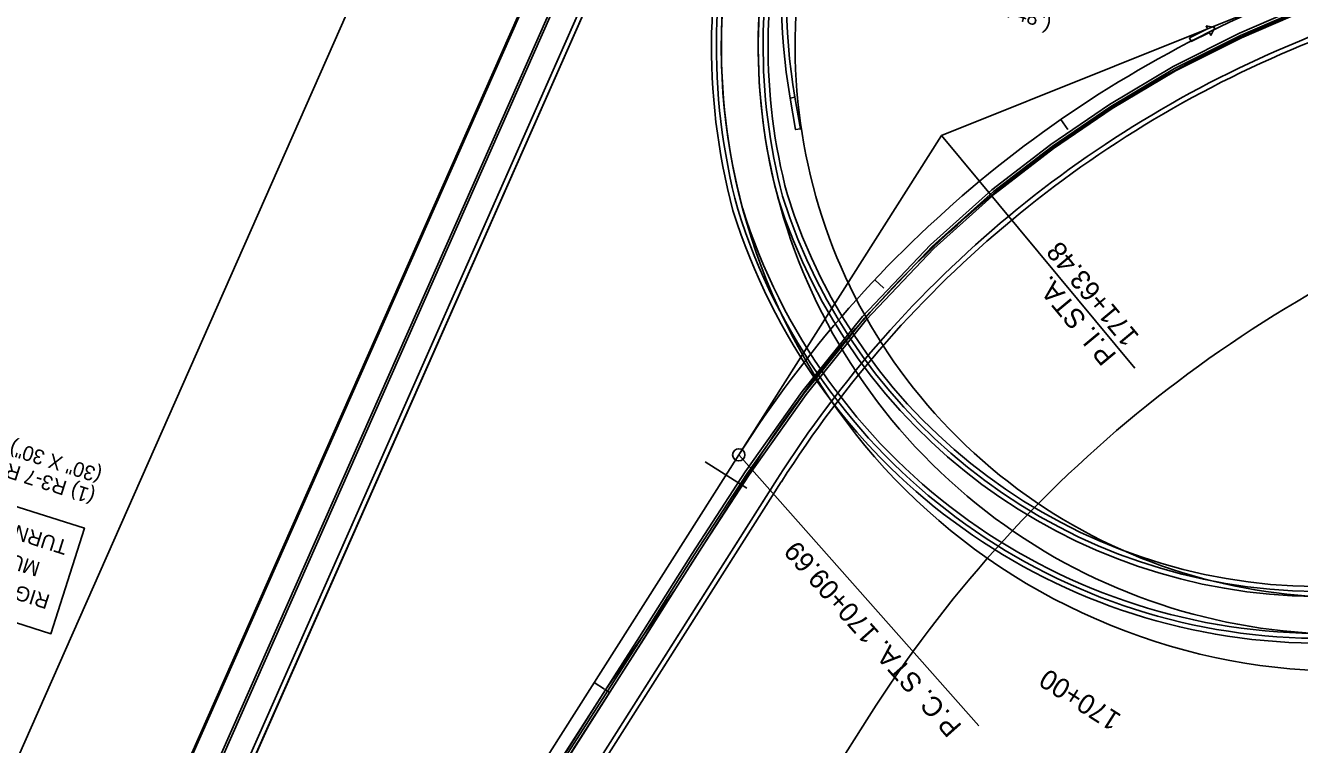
# Model space of a CAD drawing. Extents: x 659657 to 668193, y 633084 to 648639.
# Drawn here: x 661821 to 662339, y 641864 to 642156 of the extents above; entities that cross this region are included whole.
import ezdxf

# ---------------------------------------------------------------- set-up
doc = ezdxf.new("R2010")
doc.units = 0
for name, color, linetype in [('R_Border Prem', 7, 'Continuous'), ('R_MOT_Stage 1A', 7, 'Continuous'), ('R_MOT_Stage 1A_Striping', 7, 'Continuous'), ('R_MOT_Stage 1B', 7, 'Continuous'), ('R_MOT_Stage 1B_Striping', 7, 'Continuous'), ('R_MOT_Stage 1C', 7, 'Continuous'), ('R_MOT_Stage 1C_Striping', 7, 'Continuous'), ('R_MOT_Stage 2', 7, 'Continuous'), ('R_MOT_Stage 2_Striping', 7, 'Continuous'), ('R_MOT_Stage 3', 7, 'Continuous'), ('R_MOT_Stage 3_Striping', 7, 'Continuous'), ('R_MOT_Stage 3_Striping_PPM', 7, 'Continuous'), ('R_MOT_Stage 4', 7, 'Continuous'), ('R_MOT_Stage 4_Striping', 7, 'Continuous'), ('R_MOT_Stage 4_Striping_PPM', 7, 'Continuous'), ('R_MOT_Stage 5_Striping_PPM', 7, 'Continuous'), ('R_ROW Annot', 7, 'Continuous'), ('S_EXISTING_ALIGNMENT', 7, 'Continuous'), ('T_SIGNAL CONTROL CABINET', 7, 'Continuous'), ('TEMP_SIGNAL_POLES_STAGE 3', 7, 'Continuous')]:
    doc.layers.add(name, color=color, linetype=linetype)

msp = doc.modelspace()

# ---------------------------------------------------------------- linework, layer by layer
at = {"layer": 'R_Border Prem'}
msp.add_line((661686.79, 641562.92), (662861.91, 644217.67), dxfattribs=at)
at = {"layer": 'R_MOT_Stage 1A'}
for points in [[(662027.38, 641840.52), (662048.99, 641874.22), (662070.58, 641907.89), (662092.01, 641941.66), (662113.5, 641974.84), (662136.77, 642007.5), (662161.29, 642037.97), (662188.9, 642067.14), (662213.92, 642089.54), (662237.82, 642107.91), (662261.72, 642124.18), (662287.62, 642139.66), (662314.59, 642153.12), (662341.29, 642164.63), (662369.17, 642175.81), (662397.15, 642186.64), (662412.11, 642192.63), (662439.78, 642204.17), (662466.92, 642216.62), (662485.76, 642227.77), (662499, 642237.13)], [(662029.07, 641839.44), (662050.67, 641873.14), (662072.26, 641906.81), (662093.7, 641940.58), (662115.16, 641973.72), (662138.37, 642006.29), (662162.79, 642036.66), (662190.29, 642065.71), (662215.2, 642088), (662238.99, 642106.29), (662262.8, 642122.49), (662288.59, 642137.9), (662315.44, 642151.3), (662342.06, 642162.78), (662369.91, 642173.95), (662397.88, 642184.78), (662412.86, 642190.78), (662440.59, 642202.33), (662467.85, 642214.84), (662486.85, 642226.09), (662500.16, 642235.5)]]:
    msp.add_lwpolyline(points, dxfattribs=at)
at = {"layer": 'R_MOT_Stage 1A_Striping'}
for p, q in [((662193.45, 642111.58), (662336.18, 642168.83)), ((662193.45, 642111.58), (662336.18, 642168.83)), ((662110.96, 641981.8), (662193.45, 642111.58)), ((662110.96, 641981.8), (662193.45, 642111.58)), ((661764.81, 641437.19), (662110.96, 641981.8))]:
    msp.add_line(p, q, dxfattribs=at)
for points in [[(662027.38, 641840.52), (662048.99, 641874.22), (662070.58, 641907.89), (662092.01, 641941.66), (662113.5, 641974.84), (662136.77, 642007.5), (662161.29, 642037.97), (662188.9, 642067.14), (662213.92, 642089.54), (662237.82, 642107.91), (662261.72, 642124.18), (662287.62, 642139.66), (662314.59, 642153.12), (662341.29, 642164.63), (662369.17, 642175.81), (662397.15, 642186.64), (662412.11, 642192.63), (662439.78, 642204.17), (662466.92, 642216.62), (662485.76, 642227.77), (662499, 642237.13)], [(662244.79, 642114), (662241.95, 642118.11)], [(662193.45, 642111.58), (662272.02, 642016.97)], [(662169.94, 642049.56), (662166.3, 642052.99)], [(662110.96, 641981.8), (662208.63, 641871.7)], [(662097.32, 641978.98), (662114.2, 641968.25)], [(662056.34, 641886.54), (662052.12, 641889.22)]]:
    msp.add_lwpolyline(points, dxfattribs=at)
msp.add_circle((662110.96, 641981.8), 2.5, dxfattribs=at)
msp.add_arc((662513.92, 641725.68), 477.46, 111.8548, 147.5604, dxfattribs=at)
at = {"layer": 'R_MOT_Stage 1B'}
for p, q in [((662096.24, 641920.42), (662128.26, 641970.8)), ((662029.07, 641814.74), (662096.24, 641920.42)), ((661828.79, 641527.59), (662056.76, 641886.27)), ((661830.47, 641526.51), (662058.45, 641885.2)), ((662058.45, 641885.2), (662056.76, 641886.27))]:
    msp.add_line(p, q, dxfattribs=at)
msp.add_arc((662513.92, 641725.68), 456.96, 111.8548, 147.5604, dxfattribs=at)
at = {"layer": 'R_MOT_Stage 1B_Striping'}
for p, q in [((662193.45, 642111.58), (662336.18, 642168.83)), ((662193.45, 642111.58), (662336.18, 642168.83)), ((662110.96, 641981.8), (662193.45, 642111.58)), ((662110.96, 641981.8), (662193.45, 642111.58)), ((661764.81, 641437.19), (662110.96, 641981.8)), ((662085.27, 641927.4), (662117.29, 641977.78)), ((662094.55, 641921.49), (662126.57, 641971.87)), ((662018.1, 641821.71), (662085.27, 641927.4)), ((662056.76, 641886.27), (662085.27, 641927.4)), ((662027.38, 641815.81), (662094.55, 641921.49)), ((661796.6, 641476.95), (662056.76, 641886.27))]:
    msp.add_line(p, q, dxfattribs=at)
for points in [[(662244.79, 642114), (662241.95, 642118.11)], [(662193.45, 642111.58), (662272.02, 642016.97)], [(662169.94, 642049.56), (662166.3, 642052.99)], [(662110.96, 641981.8), (662208.63, 641871.7)], [(662097.32, 641978.98), (662114.2, 641968.25)], [(662056.34, 641886.54), (662052.12, 641889.22)]]:
    msp.add_lwpolyline(points, dxfattribs=at)
msp.add_circle((662110.96, 641981.8), 2.5, dxfattribs=at)
for radius in [477.46, 469.96, 458.96]:
    msp.add_arc((662513.92, 641725.68), radius, 111.8548, 147.5604, dxfattribs=at)
at = {"layer": 'R_MOT_Stage 1C'}
msp.add_line((662025.12, 641808.53), (662128.26, 641970.8), dxfattribs=at)
msp.add_arc((662513.92, 641725.68), 456.96, 111.8548, 147.5604, dxfattribs=at)
at = {"layer": 'R_MOT_Stage 1C_Striping'}
for p, q in [((662085.27, 641927.4), (662117.29, 641977.78)), ((662023.47, 641809.66), (662126.57, 641971.87)), ((662025.03, 641832.62), (662085.27, 641927.4))]:
    msp.add_line(p, q, dxfattribs=at)
for radius in [469.96, 458.96]:
    msp.add_arc((662513.92, 641725.68), radius, 111.8548, 147.5604, dxfattribs=at)
at = {"layer": 'R_MOT_Stage 2'}
msp.add_lwpolyline([(662645.5, 643511.36), (661880.49, 641783.11), (661878.66, 641783.92), (662643.67, 643512.17)], close=True, dxfattribs=at)
at = {"layer": 'R_MOT_Stage 2_Striping'}
for p, q in [((662653.91, 643589.66), (661803.9, 641669.37)), ((661813.96, 641664.92), (662663.97, 643585.2))]:
    msp.add_line(p, q, dxfattribs=at)
msp.add_lwpolyline([(661878.66, 641783.92), (662674.03, 643580.75)], dxfattribs=at)
at = {"layer": 'R_MOT_Stage 3'}
msp.add_lwpolyline([(662136.01, 642114.34), (662133.8, 642127.15), (662131.83, 642126.8), (662134.04, 642113.99)], close=True, dxfattribs=at)
for centre, radius, start, end in [((662357.6, 642147.63), 255.73, 162.4818, 194.9542), ((662357.6, 642147.63), 236.73, 164.2267, 194.8584), ((662365.1, 642167.13), 236.73, 169.2401, 189.8087), ((662365.1, 642167.13), 234.73, 169.2401, 189.8087), ((662347.7, 642155.68), 229.46, 197.4365, 269.4365), ((662347.7, 642155.68), 248.46, 197.3379, 269.338)]:
    msp.add_arc(centre, radius, start, end, dxfattribs=at)
at = {"layer": 'R_MOT_Stage 3_Striping'}
for centre, radius, start, end in [((662357.6, 642147.63), 253.73, 162.4818, 194.9448), ((662357.6, 642147.63), 238.73, 164.2267, 194.8692), ((662347.7, 642155.68), 231.46, 197.4254, 269.4254), ((662347.7, 642155.68), 246.46, 197.3475, 269.3476)]:
    msp.add_arc(centre, radius, start, end, dxfattribs=at)
at = {"layer": 'R_MOT_Stage 3_Striping_PPM'}
for p, q in [((661859, 641792.62), (662694.85, 643680.89)), ((661869.52, 641787.96), (662705.36, 643676.24)), ((661880.49, 641783.11), (662215.01, 642538.82))]:
    msp.add_line(p, q, dxfattribs=at)
at = {"layer": 'R_MOT_Stage 4'}
msp.add_lwpolyline([(662136.01, 642114.34), (662133.8, 642127.15), (662131.83, 642126.8), (662134.04, 642113.99)], close=True, dxfattribs=at)
for radius in [236.73, 234.73]:
    msp.add_arc((662365.1, 642167.13), radius, 169.2401, 189.8087, dxfattribs=at)
at = {"layer": 'R_MOT_Stage 4_Striping'}
for centre, radius, start, end in [((662357.6, 642147.63), 253.73, 162.4818, 194.9448), ((662357.6, 642147.63), 238.73, 164.2267, 194.8692), ((662347.7, 642155.68), 231.46, 197.4254, 269.4254), ((662347.7, 642155.68), 246.46, 197.3475, 269.3476)]:
    msp.add_arc(centre, radius, start, end, dxfattribs=at)
at = {"layer": 'R_MOT_Stage 4_Striping_PPM'}
for p, q in [((661859, 641792.62), (662694.85, 643680.89)), ((661869.52, 641787.96), (662705.36, 643676.24)), ((661880.49, 641783.11), (662215.01, 642538.82))]:
    msp.add_line(p, q, dxfattribs=at)
at = {"layer": 'R_MOT_Stage 5_Striping_PPM'}
for p, q in [((661859, 641792.62), (662694.85, 643680.89)), ((661869.52, 641787.96), (662705.36, 643676.24)), ((661880.49, 641783.11), (662215.01, 642538.82))]:
    msp.add_line(p, q, dxfattribs=at)
for radius, end in [(238.73, 86.5452), (253.73, 62.8692), (223.73, 86.5452)]:
    msp.add_arc((662357.6, 642147.63), radius, 156.1234, end, dxfattribs=at)
at = {"layer": 'R_ROW Annot'}
msp.add_lwpolyline([(661788.37, 641922.69), (661831.27, 641909.1), (661844.86, 641952), (661801.96, 641965.59)], close=True, dxfattribs=at)
at = {"layer": 'S_EXISTING_ALIGNMENT'}
for p, q in [((661764.81, 641437.19), (662110.96, 641981.8)), ((662006.37, 641627.8), (662163.94, 641875.56))]:
    msp.add_line(p, q, dxfattribs=at)
for centre, radius, start, end in [((662513.92, 641725.68), 477.46, 111.8548, 147.5604), ((662603.45, 641596.04), 520.87, 110.1277, 147.5449)]:
    msp.add_arc(centre, radius, start, end, dxfattribs=at)
at = {"layer": 'T_SIGNAL CONTROL CABINET'}
for p, q in [((662301.6, 642154.96), (662294.18, 642151.28)), ((662302.35, 642153.45), (662294.93, 642149.77)), ((662300.97, 642156.22), (662301.6, 642154.96)), ((662300.97, 642156.22), (662304.59, 642155.5)), ((662302.35, 642153.45), (662302.97, 642152.19)), ((662304.59, 642155.5), (662302.97, 642152.19)), ((662294.18, 642151.28), (662294.93, 642149.77))]:
    msp.add_line(p, q, dxfattribs=at)
msp.add_lwpolyline([(662028.23, 641839.98), (662049.83, 641873.68), (662071.42, 641907.35), (662092.85, 641941.12), (662114.33, 641974.28), (662137.57, 642006.9), (662162.04, 642037.32), (662189.6, 642066.42), (662214.56, 642088.77), (662238.4, 642107.1), (662262.26, 642123.33), (662288.11, 642138.78), (662315.02, 642152.21), (662341.68, 642163.71), (662369.54, 642174.88), (662397.52, 642185.71), (662412.48, 642191.7), (662440.19, 642203.25), (662467.39, 642215.73), (662486.31, 642226.93), (662499.58, 642236.31)], dxfattribs=at)
for centre, radius, start, end in [((662357.6, 642147.63), 257.73, 162.4818, 194.9634), ((662357.6, 642147.63), 234.73, 164.2267, 194.8474), ((662347.7, 642155.68), 227.46, 197.4479, 269.4479), ((662347.7, 642155.68), 250.46, 197.3284, 269.3285)]:
    msp.add_arc(centre, radius, start, end, dxfattribs=at)
at = {"layer": 'TEMP_SIGNAL_POLES_STAGE 3'}
for p, q in [((662193.45, 642111.58), (662336.18, 642168.83)), ((662193.45, 642111.58), (662336.18, 642168.83)), ((662110.96, 641981.8), (662193.45, 642111.58)), ((662110.96, 641981.8), (662193.45, 642111.58)), ((661764.81, 641437.19), (662110.96, 641981.8))]:
    msp.add_line(p, q, dxfattribs=at)
for points in [[(662244.79, 642114), (662241.95, 642118.11)], [(662193.45, 642111.58), (662272.02, 642016.97)], [(662169.94, 642049.56), (662166.3, 642052.99)], [(662110.96, 641981.8), (662208.63, 641871.7)], [(662097.32, 641978.98), (662114.2, 641968.25)], [(662056.34, 641886.54), (662052.12, 641889.22)]]:
    msp.add_lwpolyline(points, dxfattribs=at)
msp.add_circle((662110.96, 641981.8), 2.5, dxfattribs=at)
msp.add_arc((662513.92, 641725.68), 477.46, 111.8548, 147.5604, dxfattribs=at)

# ---------------------------------------------------------------- texts
at = {"layer": 'R_MOT_Stage 1A_Striping'}
for s, rotation, p in [('171+63.48', 129.7076, (662274.13, 642030.05)), ('P.I. STA.', 129.7076, (662264.9, 642022.38)), ('P.C. STA. 170+09.69', 131.5773, (662202.02, 641871.62)), ('170+00', 147.5604, (662266.98, 641875.89))]:
    msp.add_text(s, height=8, rotation=rotation, dxfattribs=at).set_placement(p)
at = {"layer": 'R_MOT_Stage 1B_Striping'}
for s, rotation, p in [('171+63.48', 129.7076, (662274.13, 642030.05)), ('P.I. STA.', 129.7076, (662264.9, 642022.38)), ('P.C. STA. 170+09.69', 131.5773, (662202.02, 641871.62)), ('170+00', 147.5604, (662266.98, 641875.89))]:
    msp.add_text(s, height=8, rotation=rotation, dxfattribs=at).set_placement(p)
at = {"layer": 'R_ROW Annot'}
for s, height, rotation, p in [('(48" X 48")', 6, 342.9617, (662200.08, 642165.8)), ('(30" X 30")', 6, 162.4226, (661852.41, 641975.84)), ('(1) R3-7 RT.', 6, 162.4226, (661849.69, 641967.26)), ('TURN RIGHT', 6.01, 162.4226, (661838.58, 641946.76)), ('MUST', 6.01, 162.4226, (661827.33, 641937.92)), ('RIGHT LANE', 6.01, 162.4226, (661831.29, 641924.7))]:
    msp.add_text(s, height=height, rotation=rotation, dxfattribs=at).set_placement(p)
at = {"layer": 'TEMP_SIGNAL_POLES_STAGE 3'}
for s, rotation, p in [('171+63.48', 129.7076, (662274.13, 642030.05)), ('P.I. STA.', 129.7076, (662264.9, 642022.38)), ('P.C. STA. 170+09.69', 131.5773, (662202.02, 641871.62)), ('170+00', 147.5604, (662266.98, 641875.89))]:
    msp.add_text(s, height=8, rotation=rotation, dxfattribs=at).set_placement(p)

doc.saveas('drawing.dxf')
